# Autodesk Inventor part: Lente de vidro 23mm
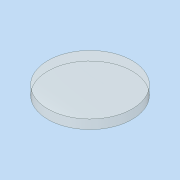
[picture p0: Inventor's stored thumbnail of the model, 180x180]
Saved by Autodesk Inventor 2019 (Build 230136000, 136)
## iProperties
Created: 2019-08
Part Number: Lente de vidro 23mm
Material: Vidro
Document SubType Name: Modeling
Designer: Usuario
Density: 2.18 g/cm^3
Appearance: Transparente
Author: Usuario
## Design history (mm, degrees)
sketch "Esboço1"
  geometry: C1 r 11.5 at (0, 0); 1 further point
  constraints: 1 centre point, 1 coincident
  dimensions: "d0" = 23 diameter of C1
extrude "Extrusão1" new body sketch "Esboço1" distance "d1" = 2.5; taper "d2" = 0 deg
node "Sólido1"
